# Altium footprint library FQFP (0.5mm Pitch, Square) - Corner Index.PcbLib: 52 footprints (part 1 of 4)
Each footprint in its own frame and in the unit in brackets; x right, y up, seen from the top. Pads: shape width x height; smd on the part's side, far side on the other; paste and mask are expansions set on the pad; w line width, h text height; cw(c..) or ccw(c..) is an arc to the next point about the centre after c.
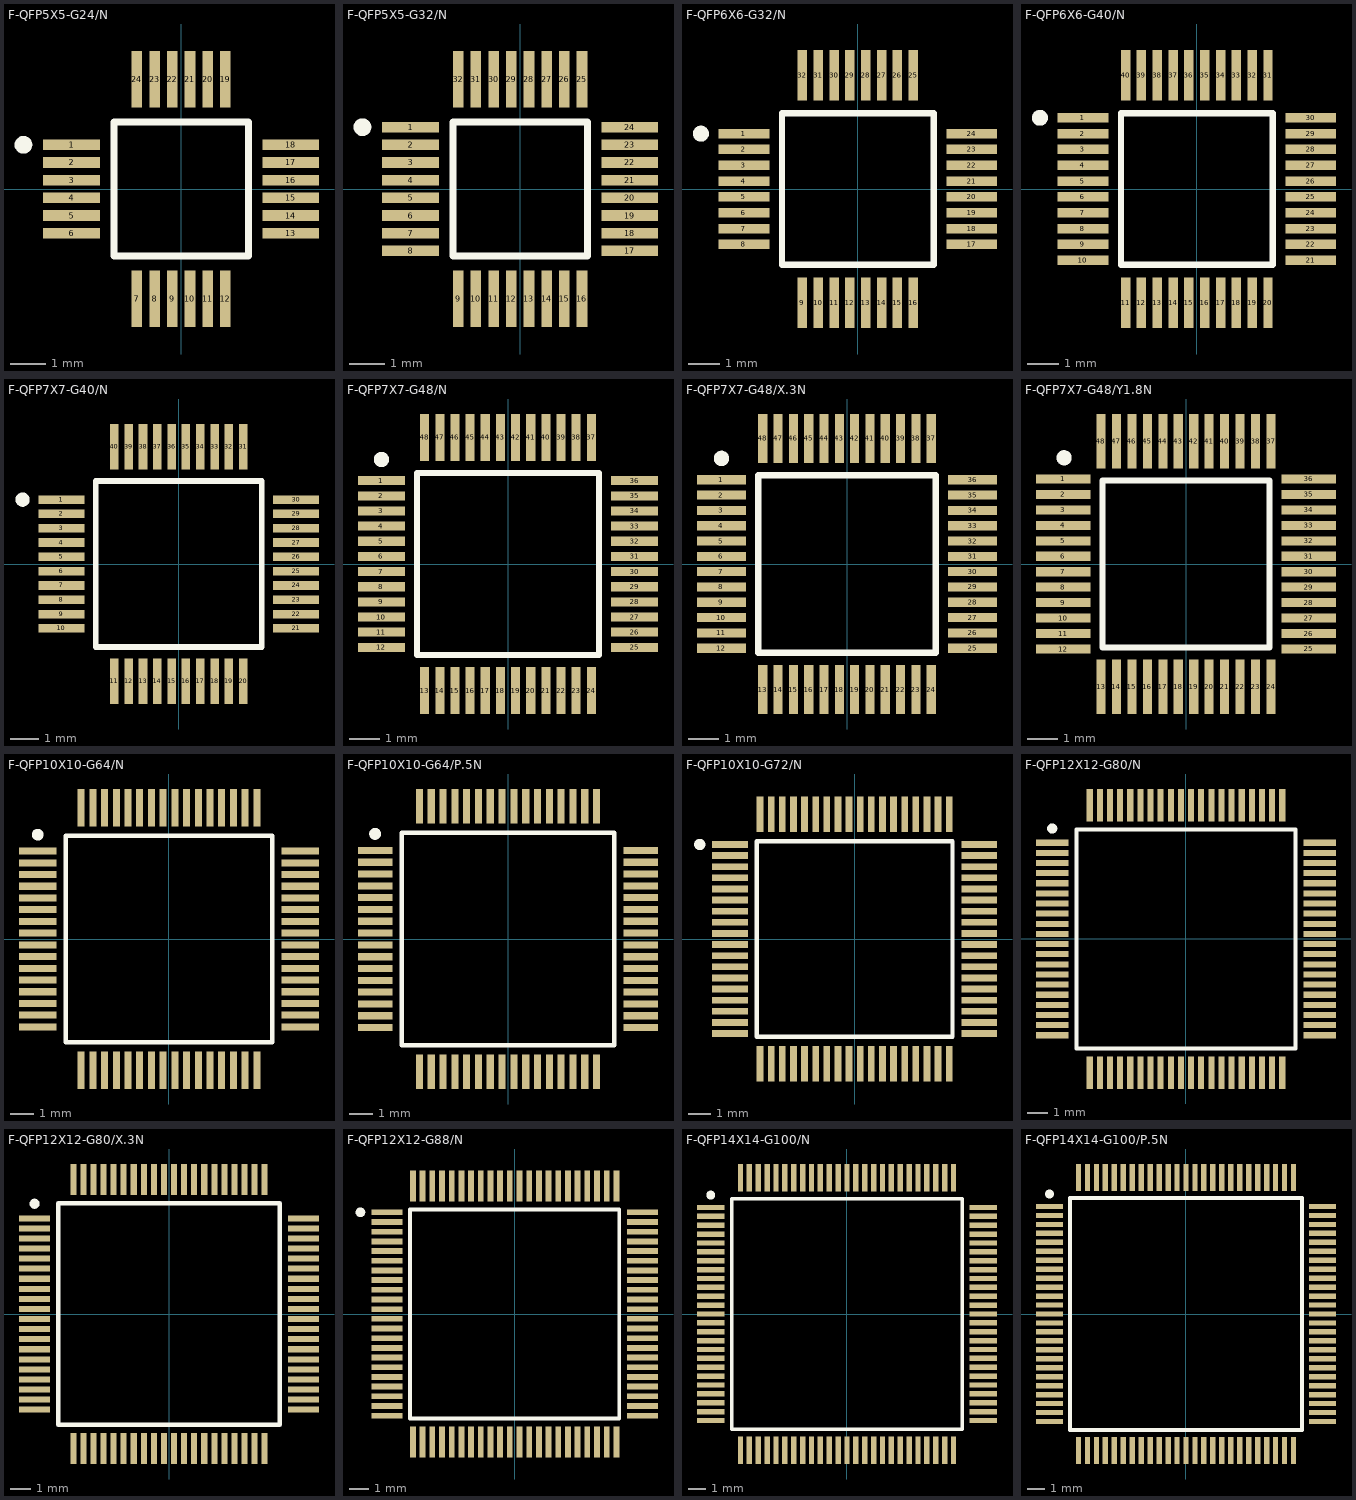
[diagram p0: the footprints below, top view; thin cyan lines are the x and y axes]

## F-QFP5X5-G24/N [mm]
pads (24):
  rect 1.6x0.3 smd: 1(-3.1,1.25) 2(-3.1,0.75) 3(-3.1,0.25) 4(-3.1,-0.25) 5(-3.1,-0.75) 6(-3.1,-1.25) 13(3.1,-1.25) 14(3.1,-0.75) 15(3.1,-0.25) 16(3.1,0.25) 17(3.1,0.75) 18(3.1,1.25)
  rect 0.3x1.6 smd: 7(-1.25,-3.1) 8(-0.75,-3.1) 9(-0.25,-3.1) 10(0.25,-3.1) 11(0.75,-3.1) 12(1.25,-3.1) 19(1.25,3.1) 20(0.75,3.1) 21(0.25,3.1) 22(-0.25,3.1) 23(-0.75,3.1) 24(-1.25,3.1)
Top Overlay:
  circle w0.25: c-4.46,1.25 r0.125
  lines w0.2: -1.9,-1.9 -1.9,1.9 1.9,1.9 1.9,-1.9 -1.9,-1.9

## F-QFP5X5-G32/N [mm]
pads (32):
  rect 1.6x0.3 smd: 1(-3.1,1.75) 2(-3.1,1.25) 3(-3.1,0.75) 4(-3.1,0.25) 5(-3.1,-0.25) 6(-3.1,-0.75) 7(-3.1,-1.25) 8(-3.1,-1.75) 17(3.1,-1.75) 18(3.1,-1.25) 19(3.1,-0.75) 20(3.1,-0.25) 21(3.1,0.25) 22(3.1,0.75) 23(3.1,1.25) 24(3.1,1.75)
  rect 0.3x1.6 smd: 9(-1.75,-3.1) 10(-1.25,-3.1) 11(-0.75,-3.1) 12(-0.25,-3.1) 13(0.25,-3.1) 14(0.75,-3.1) 15(1.25,-3.1) 16(1.75,-3.1) 25(1.75,3.1) 26(1.25,3.1) 27(0.75,3.1) 28(0.25,3.1) 29(-0.25,3.1) 30(-0.75,3.1) 31(-1.25,3.1) 32(-1.75,3.1)
Top Overlay:
  circle w0.25: c-4.46,1.75 r0.125
  lines w0.2: -1.9,-1.9 -1.9,1.9 1.9,1.9 1.9,-1.9 -1.9,-1.9

## F-QFP6X6-G32/N [mm]
pads (32):
  rect 1.6x0.3 smd: 1(-3.6,1.75) 2(-3.6,1.25) 3(-3.6,0.75) 4(-3.6,0.25) 5(-3.6,-0.25) 6(-3.6,-0.75) 7(-3.6,-1.25) 8(-3.6,-1.75) 17(3.6,-1.75) 18(3.6,-1.25) 19(3.6,-0.75) 20(3.6,-0.25) 21(3.6,0.25) 22(3.6,0.75) 23(3.6,1.25) 24(3.6,1.75)
  rect 0.3x1.6 smd: 9(-1.75,-3.6) 10(-1.25,-3.6) 11(-0.75,-3.6) 12(-0.25,-3.6) 13(0.25,-3.6) 14(0.75,-3.6) 15(1.25,-3.6) 16(1.75,-3.6) 25(1.75,3.6) 26(1.25,3.6) 27(0.75,3.6) 28(0.25,3.6) 29(-0.25,3.6) 30(-0.75,3.6) 31(-1.25,3.6) 32(-1.75,3.6)
Top Overlay:
  circle w0.25: c-4.96,1.75 r0.125
  lines w0.2: -2.4,-2.4 2.4,-2.4 2.4,2.4 -2.4,2.4 -2.4,-2.4

## F-QFP6X6-G40/N [mm]
pads (40):
  rect 1.6x0.3 smd: 1(-3.6,2.25) 2(-3.6,1.75) 3(-3.6,1.25) 4(-3.6,0.75) 5(-3.6,0.25) 6(-3.6,-0.25) 7(-3.6,-0.75) 8(-3.6,-1.25) 9(-3.6,-1.75) 10(-3.6,-2.25) 21(3.6,-2.25) 22(3.6,-1.75) 23(3.6,-1.25) 24(3.6,-0.75) 25(3.6,-0.25) 26(3.6,0.25) 27(3.6,0.75) 28(3.6,1.25) 29(3.6,1.75) 30(3.6,2.25)
  rect 0.3x1.6 smd: 11(-2.25,-3.6) 12(-1.75,-3.6) 13(-1.25,-3.6) 14(-0.75,-3.6) 15(-0.25,-3.6) 16(0.25,-3.6) 17(0.75,-3.6) 18(1.25,-3.6) 19(1.75,-3.6) 20(2.25,-3.6) 31(2.25,3.6) 32(1.75,3.6) 33(1.25,3.6) 34(0.75,3.6) 35(0.25,3.6) 36(-0.25,3.6) 37(-0.75,3.6) 38(-1.25,3.6) 39(-1.75,3.6) 40(-2.25,3.6)
Top Overlay:
  circle w0.25: c-4.96,2.25 r0.125
  lines w0.2: -2.4,-2.4 -2.4,2.4 2.4,2.4 2.4,-2.4 -2.4,-2.4

## F-QFP7X7-G40/N [mm]
pads (40):
  rect 1.6x0.3 smd: 1(-4.1,2.25) 2(-4.1,1.75) 3(-4.1,1.25) 4(-4.1,0.75) 5(-4.1,0.25) 6(-4.1,-0.25) 7(-4.1,-0.75) 8(-4.1,-1.25) 9(-4.1,-1.75) 10(-4.1,-2.25) 21(4.1,-2.25) 22(4.1,-1.75) 23(4.1,-1.25) 24(4.1,-0.75) 25(4.1,-0.25) 26(4.1,0.25) 27(4.1,0.75) 28(4.1,1.25) 29(4.1,1.75) 30(4.1,2.25)
  rect 0.3x1.6 smd: 11(-2.25,-4.1) 12(-1.75,-4.1) 13(-1.25,-4.1) 14(-0.75,-4.1) 15(-0.25,-4.1) 16(0.25,-4.1) 17(0.75,-4.1) 18(1.25,-4.1) 19(1.75,-4.1) 20(2.25,-4.1) 31(2.25,4.1) 32(1.75,4.1) 33(1.25,4.1) 34(0.75,4.1) 35(0.25,4.1) 36(-0.25,4.1) 37(-0.75,4.1) 38(-1.25,4.1) 39(-1.75,4.1) 40(-2.25,4.1)
Top Overlay:
  circle w0.25: c-5.46,2.25 r0.125
  lines w0.2: -2.9,-2.9 -2.9,2.9 2.9,2.9 2.9,-2.9 -2.9,-2.9

## F-QFP7X7-G48/N [mm]
pads (48):
  rect 1.55x0.3 smd: 1(-4.175,2.75) 2(-4.175,2.25) 3(-4.175,1.75) 4(-4.175,1.25) 5(-4.175,0.75) 6(-4.175,0.25) 7(-4.175,-0.25) 8(-4.175,-0.75) 9(-4.175,-1.25) 10(-4.175,-1.75) 11(-4.175,-2.25) 12(-4.175,-2.75) 25(4.175,-2.75) 26(4.175,-2.25) 27(4.175,-1.75) 28(4.175,-1.25) 29(4.175,-0.75) 30(4.175,-0.25) 31(4.175,0.25) 32(4.175,0.75) 33(4.175,1.25) 34(4.175,1.75) 35(4.175,2.25) 36(4.175,2.75)
  rect 0.3x1.55 smd: 13(-2.75,-4.175) 14(-2.25,-4.175) 15(-1.75,-4.175) 16(-1.25,-4.175) 17(-0.75,-4.175) 18(-0.25,-4.175) 19(0.25,-4.175) 20(0.75,-4.175) 21(1.25,-4.175) 22(1.75,-4.175) 23(2.25,-4.175) 24(2.75,-4.175) 37(2.75,4.175) 38(2.25,4.175) 39(1.75,4.175) 40(1.25,4.175) 41(0.75,4.175) 42(0.25,4.175) 43(-0.25,4.175) 44(-0.75,4.175) 45(-1.25,4.175) 46(-1.75,4.175) 47(-2.25,4.175) 48(-2.75,4.175)
Top Overlay:
  circle w0.25: c-4.175,3.45 r0.125
  lines w0.2: -3,-3 -3,3 3,3 3,-3 -3,-3

## F-QFP7X7-G48/X.3N [mm]
pads (48):
  rect 1.6x0.3 smd: 1(-4.1,2.75) 2(-4.1,2.25) 3(-4.1,1.75) 4(-4.1,1.25) 5(-4.1,0.75) 6(-4.1,0.25) 7(-4.1,-0.25) 8(-4.1,-0.75) 9(-4.1,-1.25) 10(-4.1,-1.75) 11(-4.1,-2.25) 12(-4.1,-2.75) 25(4.1,-2.75) 26(4.1,-2.25) 27(4.1,-1.75) 28(4.1,-1.25) 29(4.1,-0.75) 30(4.1,-0.25) 31(4.1,0.25) 32(4.1,0.75) 33(4.1,1.25) 34(4.1,1.75) 35(4.1,2.25) 36(4.1,2.75)
  rect 0.3x1.6 smd: 13(-2.75,-4.1) 14(-2.25,-4.1) 15(-1.75,-4.1) 16(-1.25,-4.1) 17(-0.75,-4.1) 18(-0.25,-4.1) 19(0.25,-4.1) 20(0.75,-4.1) 21(1.25,-4.1) 22(1.75,-4.1) 23(2.25,-4.1) 24(2.75,-4.1) 37(2.75,4.1) 38(2.25,4.1) 39(1.75,4.1) 40(1.25,4.1) 41(0.75,4.1) 42(0.25,4.1) 43(-0.25,4.1) 44(-0.75,4.1) 45(-1.25,4.1) 46(-1.75,4.1) 47(-2.25,4.1) 48(-2.75,4.1)
Top Overlay:
  circle w0.25: c-4.1,3.45 r0.125
  lines w0.2: -2.9,-2.9 -2.9,2.9 2.9,2.9 2.9,-2.9 -2.9,-2.9

## F-QFP7X7-G48/Y1.8N [mm]
pads (48):
  rect 1.8x0.3 smd: 1(-4.05,2.805) 2(-4.05,2.295) 3(-4.05,1.785) 4(-4.05,1.275) 5(-4.05,0.765) 6(-4.05,0.255) 7(-4.05,-0.255) 8(-4.05,-0.765) 9(-4.05,-1.275) 10(-4.05,-1.785) 11(-4.05,-2.295) 12(-4.05,-2.805) 25(4.05,-2.805) 26(4.05,-2.295) 27(4.05,-1.785) 28(4.05,-1.275) 29(4.05,-0.765) 30(4.05,-0.255) 31(4.05,0.255) 32(4.05,0.765) 33(4.05,1.275) 34(4.05,1.785) 35(4.05,2.295) 36(4.05,2.805)
  rect 0.3x1.8 smd: 13(-2.805,-4.05) 14(-2.295,-4.05) 15(-1.785,-4.05) 16(-1.275,-4.05) 17(-0.765,-4.05) 18(-0.255,-4.05) 19(0.255,-4.05) 20(0.765,-4.05) 21(1.275,-4.05) 22(1.785,-4.05) 23(2.295,-4.05) 24(2.805,-4.05) 37(2.805,4.05) 38(2.295,4.05) 39(1.785,4.05) 40(1.275,4.05) 41(0.765,4.05) 42(0.255,4.05) 43(-0.255,4.05) 44(-0.765,4.05) 45(-1.275,4.05) 46(-1.785,4.05) 47(-2.295,4.05) 48(-2.805,4.05)
Top Overlay:
  circle w0.25: c-4.025,3.505 r0.125
  lines w0.2: -2.75,-2.75 2.75,-2.75 2.75,2.75 -2.75,2.75 -2.75,-2.75

## F-QFP10X10-G64/N [mm]
pads (64):
  rect 1.6x0.3 smd: 1(-5.6,3.75) 2(-5.6,3.25) 3(-5.6,2.75) 4(-5.6,2.25) 5(-5.6,1.75) 6(-5.6,1.25) 7(-5.6,0.75) 8(-5.6,0.25) 9(-5.6,-0.25) 10(-5.6,-0.75) 11(-5.6,-1.25) 12(-5.6,-1.75) 13(-5.6,-2.25) 14(-5.6,-2.75) 15(-5.6,-3.25) 16(-5.6,-3.75) 33(5.6,-3.75) 34(5.6,-3.25) 35(5.6,-2.75) 36(5.6,-2.25) 37(5.6,-1.75) 38(5.6,-1.25) 39(5.6,-0.75) 40(5.6,-0.25) 41(5.6,0.25) 42(5.6,0.75) 43(5.6,1.25) 44(5.6,1.75) 45(5.6,2.25) 46(5.6,2.75) 47(5.6,3.25) 48(5.6,3.75)
  rect 0.3x1.6 smd: 17(-3.75,-5.6) 18(-3.25,-5.6) 19(-2.75,-5.6) 20(-2.25,-5.6) 21(-1.75,-5.6) 22(-1.25,-5.6) 23(-0.75,-5.6) 24(-0.25,-5.6) 25(0.25,-5.6) 26(0.75,-5.6) 27(1.25,-5.6) 28(1.75,-5.6) 29(2.25,-5.6) 30(2.75,-5.6) 31(3.25,-5.6) 32(3.75,-5.6) 49(3.75,5.6) 50(3.25,5.6) 51(2.75,5.6) 52(2.25,5.6) 53(1.75,5.6) 54(1.25,5.6) 55(0.75,5.6) 56(0.25,5.6) 57(-0.25,5.6) 58(-0.75,5.6) 59(-1.25,5.6) 60(-1.75,5.6) 61(-2.25,5.6) 62(-2.75,5.6) 63(-3.25,5.6) 64(-3.75,5.6)
Top Overlay:
  circle w0.25: c-5.6,4.45 r0.125
  lines w0.2: -4.4,-4.4 4.4,-4.4 4.4,4.4 -4.4,4.4 -4.4,-4.4

## F-QFP10X10-G64/P.5N [mm]
pads (64):
  rect 1.45x0.3 smd: 1(-5.625,3.75) 2(-5.625,3.25) 3(-5.625,2.75) 4(-5.625,2.25) 5(-5.625,1.75) 6(-5.625,1.25) 7(-5.625,0.75) 8(-5.625,0.25) 9(-5.625,-0.25) 10(-5.625,-0.75) 11(-5.625,-1.25) 12(-5.625,-1.75) 13(-5.625,-2.25) 14(-5.625,-2.75) 15(-5.625,-3.25) 16(-5.625,-3.75) 33(5.625,-3.75) 34(5.625,-3.25) 35(5.625,-2.75) 36(5.625,-2.25) 37(5.625,-1.75) 38(5.625,-1.25) 39(5.625,-0.75) 40(5.625,-0.25) 41(5.625,0.25) 42(5.625,0.75) 43(5.625,1.25) 44(5.625,1.75) 45(5.625,2.25) 46(5.625,2.75) 47(5.625,3.25) 48(5.625,3.75)
  rect 0.3x1.45 smd: 17(-3.75,-5.625) 18(-3.25,-5.625) 19(-2.75,-5.625) 20(-2.25,-5.625) 21(-1.75,-5.625) 22(-1.25,-5.625) 23(-0.75,-5.625) 24(-0.25,-5.625) 25(0.25,-5.625) 26(0.75,-5.625) 27(1.25,-5.625) 28(1.75,-5.625) 29(2.25,-5.625) 30(2.75,-5.625) 31(3.25,-5.625) 32(3.75,-5.625) 49(3.75,5.625) 50(3.25,5.625) 51(2.75,5.625) 52(2.25,5.625) 53(1.75,5.625) 54(1.25,5.625) 55(0.75,5.625) 56(0.25,5.625) 57(-0.25,5.625) 58(-0.75,5.625) 59(-1.25,5.625) 60(-1.75,5.625) 61(-2.25,5.625) 62(-2.75,5.625) 63(-3.25,5.625) 64(-3.75,5.625)
Top Overlay:
  circle w0.25: c-5.625,4.45 r0.125
  lines w0.2: -4.5,-4.5 -4.5,4.5 4.5,4.5 4.5,-4.5 -4.5,-4.5

## F-QFP10X10-G72/N [mm]
pads (72):
  rect 1.6x0.3 smd: 1(-5.6,4.25) 2(-5.6,3.75) 3(-5.6,3.25) 4(-5.6,2.75) 5(-5.6,2.25) 6(-5.6,1.75) 7(-5.6,1.25) 8(-5.6,0.75) 9(-5.6,0.25) 10(-5.6,-0.25) 11(-5.6,-0.75) 12(-5.6,-1.25) 13(-5.6,-1.75) 14(-5.6,-2.25) 15(-5.6,-2.75) 16(-5.6,-3.25) 17(-5.6,-3.75) 18(-5.6,-4.25) 37(5.6,-4.25) 38(5.6,-3.75) 39(5.6,-3.25) 40(5.6,-2.75) 41(5.6,-2.25) 42(5.6,-1.75) 43(5.6,-1.25) 44(5.6,-0.75) 45(5.6,-0.25) 46(5.6,0.25) 47(5.6,0.75) 48(5.6,1.25) 49(5.6,1.75) 50(5.6,2.25) 51(5.6,2.75) 52(5.6,3.25) 53(5.6,3.75) 54(5.6,4.25)
  rect 0.3x1.6 smd: 19(-4.25,-5.6) 20(-3.75,-5.6) 21(-3.25,-5.6) 22(-2.75,-5.6) 23(-2.25,-5.6) 24(-1.75,-5.6) 25(-1.25,-5.6) 26(-0.75,-5.6) 27(-0.25,-5.6) 28(0.25,-5.6) 29(0.75,-5.6) 30(1.25,-5.6) 31(1.75,-5.6) 32(2.25,-5.6) 33(2.75,-5.6) 34(3.25,-5.6) 35(3.75,-5.6) 36(4.25,-5.6) 55(4.25,5.6) 56(3.75,5.6) 57(3.25,5.6) 58(2.75,5.6) 59(2.25,5.6) 60(1.75,5.6) 61(1.25,5.6) 62(0.75,5.6) 63(0.25,5.6) 64(-0.25,5.6) 65(-0.75,5.6) 66(-1.25,5.6) 67(-1.75,5.6) 68(-2.25,5.6) 69(-2.75,5.6) 70(-3.25,5.6) 71(-3.75,5.6) 72(-4.25,5.6)
Top Overlay:
  circle w0.25: c-6.96,4.25 r0.125
  lines w0.2: -4.4,-4.4 4.4,-4.4 4.4,4.4 -4.4,4.4 -4.4,-4.4

## F-QFP12X12-G80/N [mm]
pads (80):
  rect 1.6x0.3 smd: 1(-6.6,4.75) 2(-6.6,4.25) 3(-6.6,3.75) 4(-6.6,3.25) 5(-6.6,2.75) 6(-6.6,2.25) 7(-6.6,1.75) 8(-6.6,1.25) 9(-6.6,0.75) 10(-6.6,0.25) 11(-6.6,-0.25) 12(-6.6,-0.75) 13(-6.6,-1.25) 14(-6.6,-1.75) 15(-6.6,-2.25) 16(-6.6,-2.75) 17(-6.6,-3.25) 18(-6.6,-3.75) 19(-6.6,-4.25) 20(-6.6,-4.75) 41(6.6,-4.75) 42(6.6,-4.25) 43(6.6,-3.75) 44(6.6,-3.25) 45(6.6,-2.75) 46(6.6,-2.25) 47(6.6,-1.75) 48(6.6,-1.25) 49(6.6,-0.75) 50(6.6,-0.25) 51(6.6,0.25) 52(6.6,0.75) 53(6.6,1.25) 54(6.6,1.75) 55(6.6,2.25) 56(6.6,2.75) 57(6.6,3.25) 58(6.6,3.75) 59(6.6,4.25) 60(6.6,4.75)
  rect 0.3x1.6 smd: 21(-4.75,-6.6) 22(-4.25,-6.6) 23(-3.75,-6.6) 24(-3.25,-6.6) 25(-2.75,-6.6) 26(-2.25,-6.6) 27(-1.75,-6.6) 28(-1.25,-6.6) 29(-0.75,-6.6) 30(-0.25,-6.6) 31(0.25,-6.6) 32(0.75,-6.6) 33(1.25,-6.6) 34(1.75,-6.6) 35(2.25,-6.6) 36(2.75,-6.6) 37(3.25,-6.6) 38(3.75,-6.6) 39(4.25,-6.6) 40(4.75,-6.6) 61(4.75,6.6) 62(4.25,6.6) 63(3.75,6.6) 64(3.25,6.6) 65(2.75,6.6) 66(2.25,6.6) 67(1.75,6.6) 68(1.25,6.6) 69(0.75,6.6) 70(0.25,6.6) 71(-0.25,6.6) 72(-0.75,6.6) 73(-1.25,6.6) 74(-1.75,6.6) 75(-2.25,6.6) 76(-2.75,6.6) 77(-3.25,6.6) 78(-3.75,6.6) 79(-4.25,6.6) 80(-4.75,6.6)
Top Overlay:
  circle w0.25: c-6.6,5.45 r0.125
  lines w0.2: -5.4,-5.4 5.4,-5.4 5.4,5.4 -5.4,5.4 -5.4,-5.4

## F-QFP12X12-G80/X.3N [mm]
pads (80):
  rect 1.55x0.3 smd: 1(-6.675,4.75) 2(-6.675,4.25) 3(-6.675,3.75) 4(-6.675,3.25) 5(-6.675,2.75) 6(-6.675,2.25) 7(-6.675,1.75) 8(-6.675,1.25) 9(-6.675,0.75) 10(-6.675,0.25) 11(-6.675,-0.25) 12(-6.675,-0.75) 13(-6.675,-1.25) 14(-6.675,-1.75) 15(-6.675,-2.25) 16(-6.675,-2.75) 17(-6.675,-3.25) 18(-6.675,-3.75) 19(-6.675,-4.25) 20(-6.675,-4.75) 41(6.675,-4.75) 42(6.675,-4.25) 43(6.675,-3.75) 44(6.675,-3.25) 45(6.675,-2.75) 46(6.675,-2.25) 47(6.675,-1.75) 48(6.675,-1.25) 49(6.675,-0.75) 50(6.675,-0.25) 51(6.675,0.25) 52(6.675,0.75) 53(6.675,1.25) 54(6.675,1.75) 55(6.675,2.25) 56(6.675,2.75) 57(6.675,3.25) 58(6.675,3.75) 59(6.675,4.25) 60(6.675,4.75)
  rect 0.3x1.55 smd: 21(-4.75,-6.675) 22(-4.25,-6.675) 23(-3.75,-6.675) 24(-3.25,-6.675) 25(-2.75,-6.675) 26(-2.25,-6.675) 27(-1.75,-6.675) 28(-1.25,-6.675) 29(-0.75,-6.675) 30(-0.25,-6.675) 31(0.25,-6.675) 32(0.75,-6.675) 33(1.25,-6.675) 34(1.75,-6.675) 35(2.25,-6.675) 36(2.75,-6.675) 37(3.25,-6.675) 38(3.75,-6.675) 39(4.25,-6.675) 40(4.75,-6.675) 61(4.75,6.675) 62(4.25,6.675) 63(3.75,6.675) 64(3.25,6.675) 65(2.75,6.675) 66(2.25,6.675) 67(1.75,6.675) 68(1.25,6.675) 69(0.75,6.675) 70(0.25,6.675) 71(-0.25,6.675) 72(-0.75,6.675) 73(-1.25,6.675) 74(-1.75,6.675) 75(-2.25,6.675) 76(-2.75,6.675) 77(-3.25,6.675) 78(-3.75,6.675) 79(-4.25,6.675) 80(-4.75,6.675)
Top Overlay:
  circle w0.25: c-6.675,5.475 r0.125
  lines w0.2: -5.5,-5.5 -5.5,5.5 5.5,5.5 5.5,-5.5 -5.5,-5.5

## F-QFP12X12-G88/N [mm]
pads (88):
  rect 1.6x0.3 smd: 1(-6.6,5.25) 2(-6.6,4.75) 3(-6.6,4.25) 4(-6.6,3.75) 5(-6.6,3.25) 6(-6.6,2.75) 7(-6.6,2.25) 8(-6.6,1.75) 9(-6.6,1.25) 10(-6.6,0.75) 11(-6.6,0.25) 12(-6.6,-0.25) 13(-6.6,-0.75) 14(-6.6,-1.25) 15(-6.6,-1.75) 16(-6.6,-2.25) 17(-6.6,-2.75) 18(-6.6,-3.25) 19(-6.6,-3.75) 20(-6.6,-4.25) 21(-6.6,-4.75) 22(-6.6,-5.25) 45(6.6,-5.25) 46(6.6,-4.75) 47(6.6,-4.25) 48(6.6,-3.75) 49(6.6,-3.25) 50(6.6,-2.75) 51(6.6,-2.25) 52(6.6,-1.75) 53(6.6,-1.25) 54(6.6,-0.75) 55(6.6,-0.25) 56(6.6,0.25) 57(6.6,0.75) 58(6.6,1.25) 59(6.6,1.75) 60(6.6,2.25) 61(6.6,2.75) 62(6.6,3.25) 63(6.6,3.75) 64(6.6,4.25) 65(6.6,4.75) 66(6.6,5.25)
  rect 0.3x1.6 smd: 23(-5.25,-6.6) 24(-4.75,-6.6) 25(-4.25,-6.6) 26(-3.75,-6.6) 27(-3.25,-6.6) 28(-2.75,-6.6) 29(-2.25,-6.6) 30(-1.75,-6.6) 31(-1.25,-6.6) 32(-0.75,-6.6) 33(-0.25,-6.6) 34(0.25,-6.6) 35(0.75,-6.6) 36(1.25,-6.6) 37(1.75,-6.6) 38(2.25,-6.6) 39(2.75,-6.6) 40(3.25,-6.6) 41(3.75,-6.6) 42(4.25,-6.6) 43(4.75,-6.6) 44(5.25,-6.6) 67(5.25,6.6) 68(4.75,6.6) 69(4.25,6.6) 70(3.75,6.6) 71(3.25,6.6) 72(2.75,6.6) 73(2.25,6.6) 74(1.75,6.6) 75(1.25,6.6) 76(0.75,6.6) 77(0.25,6.6) 78(-0.25,6.6) 79(-0.75,6.6) 80(-1.25,6.6) 81(-1.75,6.6) 82(-2.25,6.6) 83(-2.75,6.6) 84(-3.25,6.6) 85(-3.75,6.6) 86(-4.25,6.6) 87(-4.75,6.6) 88(-5.25,6.6)
Top Overlay:
  circle w0.25: c-7.96,5.25 r0.125
  lines w0.2: -5.4,-5.4 -5.4,5.4 5.4,5.4 5.4,-5.4 -5.4,-5.4

## F-QFP14X14-G100/N [mm]
pads (100):
  rect 1.55x0.3 smd: 1(-7.675,6) 2(-7.675,5.5) 3(-7.675,5) 4(-7.675,4.5) 5(-7.675,4) 6(-7.675,3.5) 7(-7.675,3) 8(-7.675,2.5) 9(-7.675,2) 10(-7.675,1.5) 11(-7.675,1) 12(-7.675,0.5) 13(-7.675,0) 14(-7.675,-0.5) 15(-7.675,-1) 16(-7.675,-1.5) 17(-7.675,-2) 18(-7.675,-2.5) 19(-7.675,-3) 20(-7.675,-3.5) 21(-7.675,-4) 22(-7.675,-4.5) 23(-7.675,-5) 24(-7.675,-5.5) 25(-7.675,-6) 51(7.675,-6) 52(7.675,-5.5) 53(7.675,-5) 54(7.675,-4.5) 55(7.675,-4) 56(7.675,-3.5) 57(7.675,-3) 58(7.675,-2.5) 59(7.675,-2) 60(7.675,-1.5) 61(7.675,-1) 62(7.675,-0.5) 63(7.675,0) 64(7.675,0.5) 65(7.675,1) 66(7.675,1.5) 67(7.675,2) 68(7.675,2.5) 69(7.675,3) 70(7.675,3.5) 71(7.675,4) 72(7.675,4.5) 73(7.675,5) 74(7.675,5.5) 75(7.675,6)
  rect 0.3x1.55 smd: 26(-6,-7.675) 27(-5.5,-7.675) 28(-5,-7.675) 29(-4.5,-7.675) 30(-4,-7.675) 31(-3.5,-7.675) 32(-3,-7.675) 33(-2.5,-7.675) 34(-2,-7.675) 35(-1.5,-7.675) 36(-1,-7.675) 37(-0.5,-7.675) 38(0,-7.675) 39(0.5,-7.675) 40(1,-7.675) 41(1.5,-7.675) 42(2,-7.675) 43(2.5,-7.675) 44(3,-7.675) 45(3.5,-7.675) 46(4,-7.675) 47(4.5,-7.675) 48(5,-7.675) 49(5.5,-7.675) 50(6,-7.675) 76(6,7.675) 77(5.5,7.675) 78(5,7.675) 79(4.5,7.675) 80(4,7.675) 81(3.5,7.675) 82(3,7.675) 83(2.5,7.675) 84(2,7.675) 85(1.5,7.675) 86(1,7.675) 87(0.5,7.675) 88(0,7.675) 89(-0.5,7.675) 90(-1,7.675) 91(-1.5,7.675) 92(-2,7.675) 93(-2.5,7.675) 94(-3,7.675) 95(-3.5,7.675) 96(-4,7.675) 97(-4.5,7.675) 98(-5,7.675) 99(-5.5,7.675) 100(-6,7.675)
Top Overlay:
  circle w0.25: c-7.675,6.7 r0.125
  lines w0.2: -6.5,-6.5 6.5,-6.5 6.5,6.5 -6.5,6.5 -6.5,-6.5

## F-QFP14X14-G100/P.5N [mm]
pads (100):
  rect 1.5x0.3 smd: 1(-7.625,6) 2(-7.625,5.5) 3(-7.625,5) 4(-7.625,4.5) 5(-7.625,4) 6(-7.625,3.5) 7(-7.625,3) 8(-7.625,2.5) 9(-7.625,2) 10(-7.625,1.5) 11(-7.625,1) 12(-7.625,0.5) 13(-7.625,0) 14(-7.625,-0.5) 15(-7.625,-1) 16(-7.625,-1.5) 17(-7.625,-2) 18(-7.625,-2.5) 19(-7.625,-3) 20(-7.625,-3.5) 21(-7.625,-4) 22(-7.625,-4.5) 23(-7.625,-5) 24(-7.625,-5.5) 25(-7.625,-6) 51(7.625,-6) 52(7.625,-5.5) 53(7.625,-5) 54(7.625,-4.5) 55(7.625,-4) 56(7.625,-3.5) 57(7.625,-3) 58(7.625,-2.5) 59(7.625,-2) 60(7.625,-1.5) 61(7.625,-1) 62(7.625,-0.5) 63(7.625,0) 64(7.625,0.5) 65(7.625,1) 66(7.625,1.5) 67(7.625,2) 68(7.625,2.5) 69(7.625,3) 70(7.625,3.5) 71(7.625,4) 72(7.625,4.5) 73(7.625,5) 74(7.625,5.5) 75(7.625,6)
  rect 0.3x1.5 smd: 26(-6,-7.625) 27(-5.5,-7.625) 28(-5,-7.625) 29(-4.5,-7.625) 30(-4,-7.625) 31(-3.5,-7.625) 32(-3,-7.625) 33(-2.5,-7.625) 34(-2,-7.625) 35(-1.5,-7.625) 36(-1,-7.625) 37(-0.5,-7.625) 38(0,-7.625) 39(0.5,-7.625) 40(1,-7.625) 41(1.5,-7.625) 42(2,-7.625) 43(2.5,-7.625) 44(3,-7.625) 45(3.5,-7.625) 46(4,-7.625) 47(4.5,-7.625) 48(5,-7.625) 49(5.5,-7.625) 50(6,-7.625) 76(6,7.625) 77(5.5,7.625) 78(5,7.625) 79(4.5,7.625) 80(4,7.625) 81(3.5,7.625) 82(3,7.625) 83(2.5,7.625) 84(2,7.625) 85(1.5,7.625) 86(1,7.625) 87(0.5,7.625) 88(0,7.625) 89(-0.5,7.625) 90(-1,7.625) 91(-1.5,7.625) 92(-2,7.625) 93(-2.5,7.625) 94(-3,7.625) 95(-3.5,7.625) 96(-4,7.625) 97(-4.5,7.625) 98(-5,7.625) 99(-5.5,7.625) 100(-6,7.625)
Top Overlay:
  circle w0.25: c-7.625,6.7 r0.125
  lines w0.2: -6.475,-6.475 6.475,-6.475 6.475,6.475 -6.475,6.475 -6.475,-6.475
